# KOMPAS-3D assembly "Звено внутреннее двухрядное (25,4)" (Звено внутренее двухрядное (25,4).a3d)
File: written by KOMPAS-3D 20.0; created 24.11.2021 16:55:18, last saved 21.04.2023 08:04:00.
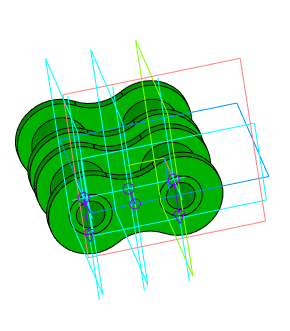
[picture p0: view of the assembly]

Document properties: Полное имя файла: C:\!WORK!\ЗИГ-18.240.00 Линия ЗигЗаг\Цепь\Звено внутренее двухрядное (25,4).a3d

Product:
- Part/product: Звено внутреннее двухрядное (25,4)
    Масса: 0.150139
  - Component [assembly]: Звено внутреннее однорядное (25,4)  | qty 2  | Масса: 0.0750693; source file: Звено внутреннее однорядное (25,4).a3d

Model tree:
1. Средняя плоскость:1  (with: Элемент выдавливания:1)
2. Ось конической поверхности:1  (with: Элемент выдавливания:1)
3. Ось конической поверхности:2  (with: Элемент выдавливания:1)
4. Ось на пересечении двух плоскостей:1
5. Смещенная плоскость:1
     Расстояние = 25.4
6. Ось на пересечении двух плоскостей:2
7. Присоединительная точка:3
     Координата X = 14.645
8. Присоединительная точка:4
9. Средняя плоскость:2
10. Ось через две точки:1
11. Ось на пересечении двух плоскостей:3
12. Присоединительная точка:5  (with: Элемент выдавливания:1)
     Расстояние = 6.89

Referenced files in C:\!WORK!\ЗИГ-18.240.00 Линия ЗигЗаг\Цепь\: Звено внутреннее однорядное (25,4).a3d
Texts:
  SAPR-SVARKA-38 docBasicParam
  SAPR-SVARKA-38 docBodyParam
  SAPR-SVARKA-38 docWeldSignParam
  Звено внутреннее однорядное (25,4) (1)
  Звено внутреннее однорядное (25,4) (2)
